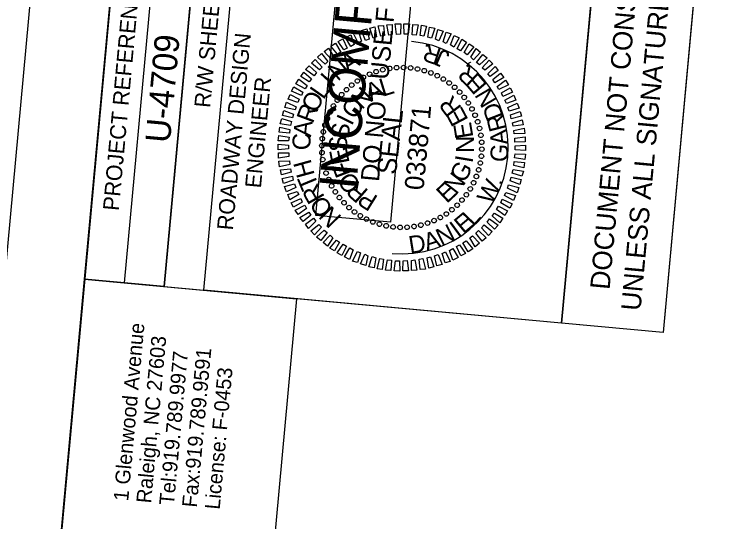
# Model space of a CAD drawing. Extents: x 2012234 to 2013485, y 445892 to 447846.
# Drawn here: x 2012372.3 to 2012600.1, y 447543.6 to 447702.6 of the extents above; entities that cross this region are included whole.
import ezdxf

# ---------------------------------------------------------------- set-up
doc = ezdxf.new("R2010")
doc.units = 0
for name, color, linetype in [('Old_Level_2', 7, 'Continuous'), ('Old_Level_58', 7, 'Continuous'), ('Scratch_Level_0', 7, 'Continuous'), ('Sheet Clip Boundary CELL', 7, 'Continuous'), ('Sheet Data Field CELL', 7, 'Continuous'), ('Sheet Plan And Profile CELL', 7, 'Continuous'), ('Sheet Plot Border Outside CELL', 7, 'Continuous'), ('Sheet Professional Seal CELL', 7, 'Continuous'), ('Sheet Profile Grid Minor CELL', 7, 'Continuous'), ('Sheet Sticker Exception Certification CELL', 7, 'Continuous'), ('Sheet Sticker Incomplete CELL', 7, 'Continuous')]:
    doc.layers.add(name, color=color, linetype=linetype)

msp = doc.modelspace()

# ---------------------------------------------------------------- linework, layer by layer
at = {"layer": 'Old_Level_58'}
msp.add_lwpolyline([(2012375.92, 447420.36), (2012394.24, 447619.57), (2012460.65, 447613.46), (2012442.33, 447414.25)], close=True, dxfattribs=at)
at = {"layer": 'Scratch_Level_0'}
msp.add_arc((2012493.64, 447660.9), 33.36, 264.7467, 84.7467, dxfattribs=at)
at = {"layer": 'Sheet Clip Boundary CELL'}
msp.add_lwpolyline([(2012286.31, 446445.78), (2012511.43, 446429.21), (2012750.66, 446410.08), (2013333.05, 446362.08), (2013458.14, 447722.64), (2012593.82, 447802.11), (2012575.5, 447602.9), (2012460.65, 447613.46), (2012442.34, 447414.28), (2012375.93, 447420.39)], close=True, dxfattribs=at)
at = {"layer": 'Sheet Plan And Profile CELL'}
for p, q in [((2012406.74, 447618.42), (2012425.05, 447817.63)), ((2012419.18, 447617.27), (2012437.5, 447816.48)), ((2012419.18, 447617.27), (2012431.63, 447616.13)), ((2012419.18, 447617.27), (2012431.63, 447616.13))]:
    msp.add_line(p, q, dxfattribs=at)
for points in [[(2012412.56, 447818.78), (2012275.22, 446325.08), (2013320.81, 446228.94), (2013458.14, 447722.64)], [(2012394.24, 447619.57), (2012412.56, 447818.78), (2012437.5, 447816.48), (2012419.18, 447617.27)], [(2012431.63, 447616.13), (2012440.79, 447715.76), (2012552.82, 447705.46), (2012543.66, 447605.83)]]:
    msp.add_lwpolyline(points, close=True, dxfattribs=at)
at = {"layer": 'Sheet Plot Border Outside CELL'}
msp.add_lwpolyline([(2013329.68, 446052.39), (2013485.33, 447745.24), (2012389.95, 447845.96), (2012234.3, 446153.1)], close=True, dxfattribs=at)
at = {"layer": 'Sheet Professional Seal CELL'}
for p, q in [((2012487.65, 447685.3), (2012487.65, 447685.3)), ((2012489.79, 447685.7), (2012489.79, 447685.7)), ((2012492.02, 447685.9), (2012492.02, 447685.9)), ((2012494.19, 447686), (2012494.19, 447686)), ((2012496.39, 447685.85), (2012496.39, 447685.85)), ((2012498.56, 447685.5), (2012498.56, 447685.5)), ((2012481.55, 447682.9), (2012481.55, 447682.9)), ((2012483.55, 447683.87), (2012483.55, 447683.87)), ((2012485.58, 447684.68), (2012485.58, 447684.68)), ((2012500.67, 447684.95), (2012500.67, 447684.95)), ((2012502.72, 447684.31), (2012502.72, 447684.31)), ((2012504.75, 447683.42), (2012504.75, 447683.42)), ((2012479.7, 447681.81), (2012479.7, 447681.81)), ((2012506.66, 447682.34), (2012506.66, 447682.34)), ((2012508.51, 447681.17), (2012508.51, 447681.17)), ((2012476.28, 447679.06), (2012476.28, 447679.06)), ((2012477.92, 447680.47), (2012477.92, 447680.47)), ((2012510.19, 447679.76), (2012510.19, 447679.76)), ((2012474.78, 447677.44), (2012474.78, 447677.44)), ((2012511.81, 447678.26), (2012511.81, 447678.26)), ((2012513.21, 447676.62), (2012513.21, 447676.62)), ((2012472.19, 447673.91), (2012472.19, 447673.91)), ((2012473.37, 447675.76), (2012473.37, 447675.76)), ((2012514.55, 447674.84), (2012514.55, 447674.84)), ((2012471.11, 447672.01), (2012471.11, 447672.01)), ((2012515.64, 447672.98), (2012515.64, 447672.98)), ((2012470.22, 447669.98), (2012470.22, 447669.98)), ((2012516.61, 447670.99), (2012516.61, 447670.99)), ((2012469.58, 447667.93), (2012469.58, 447667.93)), ((2012517.43, 447668.95), (2012517.43, 447668.95)), ((2012518.04, 447666.89), (2012518.04, 447666.89)), ((2012469.04, 447665.82), (2012469.04, 447665.82)), ((2012518.45, 447664.74), (2012518.45, 447664.74)), ((2012468.69, 447663.64), (2012468.69, 447663.64)), ((2012518.64, 447662.51), (2012518.64, 447662.51)), ((2012468.53, 447661.45), (2012468.53, 447661.45)), ((2012493.64, 447660.9), (2012493.64, 447660.9)), ((2012518.74, 447660.35), (2012518.74, 447660.35)), ((2012468.64, 447659.28), (2012468.64, 447659.28)), ((2012518.59, 447658.15), (2012518.59, 447658.15)), ((2012468.83, 447657.05), (2012468.83, 447657.05)), ((2012518.24, 447655.97), (2012518.24, 447655.97)), ((2012469.24, 447654.91), (2012469.24, 447654.91)), ((2012517.7, 447653.86), (2012517.7, 447653.86)), ((2012469.85, 447652.84), (2012469.85, 447652.84)), ((2012517.06, 447651.81), (2012517.06, 447651.81)), ((2012470.67, 447650.81), (2012470.67, 447650.81)), ((2012471.64, 447648.81), (2012471.64, 447648.81)), ((2012516.17, 447649.79), (2012516.17, 447649.79)), ((2012472.72, 447646.95), (2012472.72, 447646.95)), ((2012515.09, 447647.88), (2012515.09, 447647.88)), ((2012474.07, 447645.17), (2012474.07, 447645.17)), ((2012512.5, 447644.35), (2012512.5, 447644.35)), ((2012513.91, 447646.03), (2012513.91, 447646.03)), ((2012475.47, 447643.54), (2012475.47, 447643.54)), ((2012477.09, 447642.03), (2012477.09, 447642.03)), ((2012511, 447642.73), (2012511, 447642.73)), ((2012478.77, 447640.62), (2012478.77, 447640.62)), ((2012507.58, 447639.98), (2012507.58, 447639.98)), ((2012509.36, 447641.32), (2012509.36, 447641.32)), ((2012480.62, 447639.45), (2012480.62, 447639.45)), ((2012482.53, 447638.37), (2012482.53, 447638.37)), ((2012484.56, 447637.48), (2012484.56, 447637.48)), ((2012503.73, 447637.93), (2012503.73, 447637.93)), ((2012505.73, 447638.9), (2012505.73, 447638.9)), ((2012486.61, 447636.84), (2012486.61, 447636.84)), ((2012488.72, 447636.29), (2012488.72, 447636.29)), ((2012490.89, 447635.94), (2012490.89, 447635.94)), ((2012493.09, 447635.79), (2012493.09, 447635.79)), ((2012495.26, 447635.89), (2012495.26, 447635.89)), ((2012497.48, 447636.09), (2012497.48, 447636.09)), ((2012499.63, 447636.5), (2012499.63, 447636.5)), ((2012501.7, 447637.11), (2012501.7, 447637.11))]:
    msp.add_line(p, q, dxfattribs=at)
for points in [[(2012487.1, 447695.74), (2012486.25, 447699.03), (2012487.92, 447699.18), (2012488.18, 447695.99)], [(2012489.55, 447696.12), (2012488.89, 447699.34), (2012490.61, 447699.49), (2012490.62, 447696.32)], [(2012491.98, 447696.35), (2012491.58, 447699.65), (2012493.29, 447699.64), (2012493.19, 447696.44)], [(2012494.4, 447696.43), (2012494.29, 447699.7), (2012496, 447699.64), (2012495.6, 447696.42)], [(2012496.89, 447696.25), (2012497.04, 447699.5), (2012498.73, 447699.34), (2012498.08, 447696.14)], [(2012499.37, 447695.97), (2012499.77, 447699.2), (2012501.41, 447698.94), (2012500.56, 447695.76)], [(2012479.98, 447693.68), (2012478.5, 447696.63), (2012480.1, 447697.14), (2012480.99, 447694.19)], [(2012482.22, 447694.48), (2012480.99, 447697.56), (2012482.65, 447698.06), (2012483.36, 447694.88)], [(2012484.64, 447695.16), (2012483.62, 447698.32), (2012485.22, 447698.73), (2012485.73, 447695.57)], [(2012501.74, 447695.5), (2012502.33, 447698.66), (2012504.01, 447698.3), (2012502.91, 447695.14)], [(2012504.24, 447694.87), (2012504.93, 447697.92), (2012506.59, 447697.41), (2012505.25, 447694.37)], [(2012506.57, 447694), (2012507.51, 447697.03), (2012509.12, 447696.53), (2012507.58, 447693.51)], [(2012475.51, 447691.48), (2012473.65, 447694.12), (2012475.18, 447694.93), (2012476.51, 447691.99)], [(2012477.67, 447692.59), (2012476.02, 447695.4), (2012477.61, 447696.21), (2012478.73, 447693.2)], [(2012508.9, 447693.03), (2012510.08, 447696.04), (2012511.56, 447695.25), (2012509.89, 447692.39)], [(2012511, 447691.84), (2012512.42, 447694.82), (2012513.9, 447693.93), (2012512.04, 447691.24)], [(2012471.48, 447688.59), (2012469.34, 447690.95), (2012470.64, 447692.03), (2012472.35, 447689.26)], [(2012473.43, 447690.17), (2012471.4, 447692.67), (2012472.85, 447693.59), (2012474.49, 447690.77)], [(2012513.19, 447690.63), (2012514.7, 447693.35), (2012516.17, 447692.47), (2012514.09, 447689.95)], [(2012469.57, 447686.96), (2012467.17, 447689.24), (2012468.48, 447690.32), (2012470.41, 447687.84)], [(2012515.23, 447689.24), (2012516.98, 447691.89), (2012518.28, 447690.77), (2012516.05, 447688.36)], [(2012517.08, 447687.56), (2012519.02, 447690.09), (2012520.38, 447689.02), (2012517.97, 447686.83)], [(2012467.86, 447685.21), (2012465.29, 447687.3), (2012466.5, 447688.5), (2012468.64, 447686.09)], [(2012518.83, 447685.89), (2012521.01, 447688.3), (2012522.21, 447687.09), (2012519.67, 447685.11)], [(2012466.18, 447683.3), (2012463.45, 447685.31), (2012464.61, 447686.51), (2012466.87, 447684.35)], [(2012520.57, 447683.98), (2012522.84, 447686.33), (2012523.87, 447684.98), (2012521.29, 447683.11)], [(2012464.65, 447681.49), (2012461.94, 447683.09), (2012462.92, 447684.51), (2012465.34, 447682.38)], [(2012522.16, 447682.17), (2012524.55, 447684.16), (2012525.63, 447682.86), (2012522.77, 447681.16)], [(2012463.3, 447679.3), (2012460.47, 447680.82), (2012461.31, 447682.3), (2012463.95, 447680.35)], [(2012523.52, 447680.04), (2012526.1, 447681.96), (2012527.03, 447680.52), (2012524.08, 447679.04)], [(2012462.15, 447677.15), (2012459.11, 447678.58), (2012459.84, 447679.92), (2012462.6, 447678.26)], [(2012524.84, 447678.01), (2012527.55, 447679.62), (2012528.37, 447678.24), (2012525.33, 447676.86)], [(2012461.04, 447674.99), (2012458.02, 447676.02), (2012458.66, 447677.52), (2012461.49, 447676)], [(2012525.88, 447675.71), (2012528.74, 447677.3), (2012529.39, 447675.68), (2012526.39, 447674.71)], [(2012460.18, 447672.66), (2012456.99, 447673.45), (2012457.54, 447675.11), (2012460.52, 447673.68)], [(2012526.88, 447673.46), (2012529.81, 447674.79), (2012530.37, 447673.18), (2012527.23, 447672.32)], [(2012459.39, 447670.17), (2012456.25, 447670.91), (2012456.65, 447672.53), (2012459.65, 447671.35)], [(2012527.72, 447671.17), (2012530.73, 447672.2), (2012531.19, 447670.65), (2012527.91, 447669.9)], [(2012458.78, 447667.82), (2012455.56, 447668.31), (2012456.01, 447669.93), (2012459.09, 447668.99)], [(2012528.3, 447668.66), (2012531.39, 447669.53), (2012531.69, 447667.94), (2012528.55, 447667.58)], [(2012458.4, 447665.34), (2012455.16, 447665.64), (2012455.36, 447667.28), (2012458.56, 447666.53)], [(2012528.72, 447666.21), (2012531.96, 447666.96), (2012532.15, 447665.24), (2012528.88, 447665.14)], [(2012458.13, 447662.96), (2012454.87, 447663), (2012455.07, 447664.64), (2012458.29, 447664.15)], [(2012529.05, 447663.77), (2012532.31, 447664.27), (2012532.31, 447662.61), (2012529.09, 447662.56)], [(2012458.15, 447660.44), (2012454.91, 447660.19), (2012454.87, 447661.9), (2012458.11, 447661.65)], [(2012529.13, 447661.35), (2012532.37, 447661.6), (2012532.41, 447659.89), (2012529.17, 447660.14)], [(2012458.23, 447658.03), (2012454.97, 447657.52), (2012454.97, 447659.18), (2012458.19, 447659.23)], [(2012529.15, 447658.84), (2012532.41, 447658.79), (2012532.21, 447657.15), (2012528.99, 447657.65)], [(2012458.56, 447655.59), (2012455.32, 447654.83), (2012455.13, 447656.55), (2012458.4, 447656.65)], [(2012528.88, 447656.45), (2012532.12, 447656.15), (2012531.92, 447654.51), (2012528.72, 447655.26)], [(2012458.98, 447653.14), (2012455.89, 447652.27), (2012455.58, 447653.85), (2012458.73, 447654.21)], [(2012528.5, 447653.97), (2012531.72, 447653.48), (2012531.27, 447651.86), (2012528.19, 447652.8)], [(2012459.56, 447650.62), (2012456.55, 447649.59), (2012456.09, 447651.14), (2012459.37, 447651.9)], [(2012527.88, 447651.62), (2012531.03, 447650.88), (2012530.63, 447649.26), (2012527.62, 447650.44)], [(2012460.4, 447648.34), (2012457.47, 447647), (2012456.91, 447648.61), (2012460.05, 447649.47)], [(2012527.1, 447649.13), (2012530.29, 447648.34), (2012529.74, 447646.68), (2012526.76, 447648.11)], [(2012461.4, 447646.09), (2012458.54, 447644.49), (2012457.89, 447646.11), (2012460.89, 447647.09)], [(2012526.24, 447646.8), (2012529.25, 447645.77), (2012528.61, 447644.27), (2012525.79, 447645.79)], [(2012462.44, 447643.78), (2012459.73, 447642.17), (2012458.91, 447643.55), (2012461.94, 447644.93)], [(2012525.13, 447644.64), (2012528.17, 447643.21), (2012527.44, 447641.87), (2012524.68, 447643.53)], [(2012463.76, 447641.75), (2012461.17, 447639.83), (2012460.25, 447641.27), (2012463.2, 447642.76)], [(2012523.98, 447642.49), (2012526.8, 447640.98), (2012525.97, 447639.5), (2012523.33, 447641.45)], [(2012465.12, 447639.62), (2012462.73, 447637.63), (2012461.64, 447638.93), (2012464.51, 447640.63)], [(2012522.63, 447640.31), (2012525.34, 447638.7), (2012524.36, 447637.28), (2012521.94, 447639.41)], [(2012466.71, 447637.81), (2012464.44, 447635.46), (2012463.41, 447636.81), (2012465.99, 447638.68)], [(2012521.1, 447638.49), (2012523.83, 447636.48), (2012522.67, 447635.28), (2012520.4, 447637.45)], [(2012468.44, 447635.9), (2012466.26, 447633.49), (2012465.07, 447634.7), (2012467.61, 447636.68)], [(2012519.42, 447636.58), (2012521.99, 447634.49), (2012520.78, 447633.3), (2012518.64, 447635.7)], [(2012470.2, 447634.23), (2012468.26, 447631.7), (2012466.9, 447632.78), (2012469.31, 447634.96)], [(2012472.05, 447632.55), (2012470.3, 447629.9), (2012469, 447631.03), (2012471.23, 447633.43)], [(2012515.8, 447633.2), (2012517.94, 447630.84), (2012516.64, 447629.76), (2012514.93, 447632.53)], [(2012517.7, 447634.83), (2012520.11, 447632.55), (2012518.8, 447631.47), (2012516.87, 447633.96)], [(2012474.08, 447631.16), (2012472.58, 447628.44), (2012471.1, 447629.33), (2012473.19, 447631.85)], [(2012476.28, 447629.96), (2012474.85, 447626.97), (2012473.38, 447627.86), (2012475.23, 447630.55)], [(2012513.84, 447631.62), (2012515.87, 447629.13), (2012514.43, 447628.2), (2012512.78, 447631.02)], [(2012478.38, 447628.76), (2012477.2, 447625.75), (2012475.72, 447626.54), (2012477.39, 447629.4)], [(2012480.7, 447627.79), (2012479.77, 447624.76), (2012478.16, 447625.26), (2012479.7, 447628.29)], [(2012509.6, 447629.2), (2012511.25, 447626.39), (2012509.67, 447625.58), (2012508.54, 447628.6)], [(2012511.76, 447630.31), (2012513.63, 447627.68), (2012512.1, 447626.86), (2012510.76, 447629.8)], [(2012483.03, 447626.92), (2012482.35, 447623.87), (2012480.69, 447624.38), (2012482.03, 447627.42)], [(2012485.54, 447626.29), (2012484.95, 447623.13), (2012483.27, 447623.49), (2012484.36, 447626.65)], [(2012487.9, 447625.82), (2012487.51, 447622.6), (2012485.87, 447622.85), (2012486.72, 447626.03)], [(2012500.18, 447626.05), (2012501.03, 447622.76), (2012499.36, 447622.61), (2012499.1, 447625.8)], [(2012502.64, 447626.63), (2012503.65, 447623.47), (2012502.06, 447623.07), (2012501.55, 447626.23)], [(2012505.06, 447627.31), (2012506.29, 447624.23), (2012504.63, 447623.73), (2012503.92, 447626.91)], [(2012507.29, 447628.11), (2012508.78, 447625.16), (2012507.18, 447624.65), (2012506.29, 447627.6)], [(2012490.39, 447625.55), (2012490.24, 447622.3), (2012488.55, 447622.45), (2012489.19, 447625.66)], [(2012492.88, 447625.37), (2012492.98, 447622.09), (2012491.28, 447622.15), (2012491.68, 447625.38)], [(2012495.3, 447625.45), (2012495.7, 447622.14), (2012493.99, 447622.15), (2012494.09, 447625.36)], [(2012497.73, 447625.67), (2012498.39, 447622.45), (2012496.67, 447622.31), (2012496.66, 447625.47)]]:
    msp.add_lwpolyline(points, close=True, dxfattribs=at)
for centre, major_axis in [((2012485.58, 447684.65), (-0.231, 0.682)), ((2012487.68, 447685.26), (-0.171, 0.699)), ((2012489.83, 447685.68), (-0.109, 0.712)), ((2012492, 447685.92), (-0.047, 0.718)), ((2012494.19, 447685.97), (0.016, 0.72)), ((2012496.37, 447685.83), (0.078, 0.716)), ((2012498.53, 447685.49), (0.141, 0.706)), ((2012500.66, 447684.97), (0.202, 0.691)), ((2012481.58, 447682.89), (-0.346, 0.631)), ((2012483.54, 447683.85), (-0.29, 0.659)), ((2012502.73, 447684.27), (0.261, 0.671)), ((2012504.73, 447683.39), (0.318, 0.646)), ((2012506.65, 447682.34), (0.374, 0.616)), ((2012477.94, 447680.46), (-0.451, 0.562)), ((2012479.71, 447681.75), (-0.4, 0.599)), ((2012508.47, 447681.12), (0.426, 0.581)), ((2012510.18, 447679.75), (0.475, 0.541)), ((2012476.3, 447679.01), (-0.498, 0.52)), ((2012511.76, 447678.24), (0.52, 0.498)), ((2012473.41, 447675.73), (-0.581, 0.426)), ((2012474.78, 447677.43), (-0.541, 0.475)), ((2012513.2, 447676.59), (0.562, 0.451)), ((2012472.2, 447673.91), (-0.616, 0.374)), ((2012514.49, 447674.83), (0.599, 0.4)), ((2012515.63, 447672.96), (0.631, 0.346)), ((2012471.15, 447671.99), (-0.646, 0.318)), ((2012516.6, 447671), (0.659, 0.29)), ((2012470.27, 447669.99), (-0.671, 0.261)), ((2012517.39, 447668.96), (0.682, 0.231)), ((2012469.56, 447667.92), (-0.691, 0.202)), ((2012518, 447666.86), (0.699, 0.171)), ((2012469.04, 447665.79), (-0.706, 0.141)), ((2012518.43, 447664.71), (0.712, 0.109)), ((2012468.71, 447663.63), (-0.716, 0.078)), ((2012518.67, 447662.53), (0.718, 0.047)), ((2012468.57, 447661.44), (-0.72, 0.016)), ((2012518.71, 447660.35), (0.72, -0.016)), ((2012468.61, 447659.26), (-0.718, -0.047)), ((2012468.85, 447657.08), (-0.712, -0.109)), ((2012518.57, 447658.16), (0.716, -0.078)), ((2012469.28, 447654.94), (-0.699, -0.171)), ((2012518.24, 447656), (0.706, -0.141)), ((2012469.89, 447652.84), (-0.682, -0.231)), ((2012517.72, 447653.88), (0.691, -0.202)), ((2012470.68, 447650.8), (-0.659, -0.29)), ((2012517.01, 447651.8), (0.671, -0.261)), ((2012471.65, 447648.83), (-0.631, -0.346)), ((2012515.08, 447647.88), (0.616, -0.374)), ((2012516.13, 447649.8), (0.646, -0.318)), ((2012472.79, 447646.96), (-0.599, -0.4)), ((2012513.86, 447646.06), (0.581, -0.426)), ((2012474.08, 447645.2), (-0.562, -0.451)), ((2012475.52, 447643.55), (-0.52, -0.498)), ((2012512.49, 447644.36), (0.541, -0.475)), ((2012477.1, 447642.04), (-0.475, -0.541)), ((2012509.34, 447641.34), (0.451, -0.562)), ((2012510.98, 447642.78), (0.498, -0.52)), ((2012478.81, 447640.67), (-0.426, -0.581)), ((2012480.63, 447639.46), (-0.374, -0.616)), ((2012505.7, 447638.91), (0.346, -0.631)), ((2012507.57, 447640.04), (0.4, -0.599)), ((2012482.55, 447638.4), (-0.318, -0.646)), ((2012484.55, 447637.52), (-0.261, -0.671)), ((2012486.62, 447636.82), (-0.202, -0.691)), ((2012499.6, 447636.53), (0.171, -0.699)), ((2012501.7, 447637.15), (0.231, -0.682)), ((2012503.74, 447637.94), (0.29, -0.659)), ((2012488.75, 447636.3), (-0.141, -0.706)), ((2012490.91, 447635.97), (-0.078, -0.716)), ((2012493.09, 447635.82), (-0.016, -0.72)), ((2012495.28, 447635.87), (0.047, -0.718)), ((2012497.45, 447636.11), (0.109, -0.712))]:
    msp.add_ellipse(centre, major_axis=major_axis, ratio=0.999708, dxfattribs=at)
at = {"layer": 'Sheet Sticker Exception Certification CELL'}
for p, q in [((2012543.64, 447605.83), (2012561.96, 447805.04)), ((2012593.8, 447802.11), (2012575.49, 447602.9)), ((2012575.49, 447602.9), (2012543.64, 447605.83))]:
    msp.add_line(p, q, dxfattribs=at)
at = {"layer": 'Sheet Sticker Incomplete CELL'}
msp.add_lwpolyline([(2012490.08, 447637.42), (2012466.67, 447639.57), (2012480.13, 447785.95), (2012503.53, 447783.8)], close=True, dxfattribs=at)

# ---------------------------------------------------------------- texts
at = {"layer": 'Old_Level_2'}
for s, p in [('1 Glenwood Avenue', (2012407.88, 447549.82)), ('Raleigh, NC 27603', (2012415.04, 447549.16)), ('Tel:919.789.9977 ', (2012422.21, 447548.51)), ('Fax:919.789.9591', (2012429.37, 447547.85)), ('License: F-0453', (2012436.54, 447547.19))]:
    msp.add_text(s, height=4.6576, rotation=84.7467, dxfattribs=at).set_placement(p)
at = {"layer": 'Sheet Data Field CELL'}
msp.add_text('U-4709', height=7.75, rotation=84.7467, dxfattribs=at).set_placement((2012420.95, 447662.1))
at = {"layer": 'Sheet Plan And Profile CELL'}
for s, height, p in [('PROJECT REFERENCE NO.', 5.0001, (2012404.93, 447640.88)), ('R/W SHEET NO.', 5.0001, (2012433.56, 447673.19)), ('ROADWAY DESIGN', 5.0001, (2012440.68, 447634.78)), ('ENGINEER', 5, (2012449.47, 447647.98))]:
    msp.add_text(s, height=height, rotation=84.7467, dxfattribs=at).set_placement(p)
at = {"layer": 'Sheet Professional Seal CELL'}
for s, height, rotation, p in [('A', 5.64, 33.3638, (2012476.75, 447684.14)), ('N', 5.64, 40.5656, (2012473.54, 447681.47)), ('I', 5.64, 47.7668, (2012471.8, 447679.47)), ('A', 5.64, 26.5069, (2012484, 447675.14)), ('L', 5.64, 17.1475, (2012487.62, 447676.76)), ('L', 5.64, 54.9675, (2012469.04, 447675.66)), ('N', 5.64, 45.2233, (2012481.15, 447672.54)), ('O', 5.64, 62.1678, (2012466.79, 447671.45)), ('O', 5.64, 54.5801, (2012478.85, 447669.39)), ('R', 5.64, 127.2281, (2012512.61, 447673.31)), ('R', 5.64, 69.3678, (2012465.74, 447668.18)), ('E', 5.64, 117.8707, (2012514.62, 447669.56)), ('SEAL', 5.998, 83.7467, (2012491.83, 447652.17)), ('I', 5.64, 63.9363, (2012477.97, 447667.46)), ('A', 5.64, 83.767, (2012465.16, 447664.02)), ('S', 5.64, 82.6471, (2012476.88, 447663.24)), ('E', 5.64, 99.1584, (2012516.08, 447664.11)), ('C', 5.64, 90.9665, (2012465.09, 447660.06)), ('S', 5.64, 92.0023, (2012476.6, 447659.65)), ('N', 5.64, 89.803, (2012516.22, 447659.12)), ('E', 5.64, 101.3577, (2012477.33, 447656.12)), ('I', 5.64, 80.4479, (2012515.77, 447655.8)), ('H', 5.64, 105.3661, (2012466.39, 447652.31)), ('F', 5.64, 110.7137, (2012478.53, 447652.8)), ('G', 5.64, 61.7369, (2012513.27, 447649.45)), ('T', 5.64, 112.5664, (2012467.73, 447648.92)), ('O', 5.64, 129.4279, (2012481.17, 447649.24)), ('N', 5.64, 52.3806, (2012510.69, 447645.87)), ('R', 5.64, 119.7672, (2012469.61, 447645.33)), ('R', 5.64, 138.7863, (2012483.45, 447647.27)), ('E', 5.64, 43.0235, (2012507.72, 447643.13)), ('O', 5.64, 126.9684, (2012472.38, 447641.61)), ('P', 5.64, 148.1455, (2012486.49, 447645.39)), ('N', 5.64, 134.1702, (2012475.06, 447639.06))]:
    msp.add_text(s, height=height, rotation=rotation, dxfattribs=at).set_placement(p)
at = {"layer": 'Sheet Profile Grid Minor CELL'}
for s, height, rotation, p in [('R', 5.5, 162.1007, (2012506.43, 447691.83)), ('.', 5.5, 169.0272, (2012502.6, 447693.14)), ('J', 5.5, 157.2322, (2012509.01, 447690.63)), (',', 5.5, 144.0519, (2012515.38, 447686.34)), ('R', 5.5, 137.1254, (2012518.29, 447683.54)), ('E', 5.5, 130.5425, (2012520.72, 447680.56)), ('N', 5.5, 120.6107, (2012523.71, 447675.59)), ('D', 5.5, 111.4661, (2012525.66, 447670.63)), ('033871', 5.998, 84.7467, (2012500.43, 447647.32)), ('R', 5.5, 104.5397, (2012526.6, 447666.69)), ('A', 5.5, 96.3539, (2012527.09, 447661.94)), ('G', 5.5, 86.4222, (2012526.77, 447656.16)), ('W', 5.5, 61.6358, (2012521.73, 447642.7)), ('.', 5.5, 73.2419, (2012524.82, 447648.73)), ('E', 5.5, 39.7975, (2012512.95, 447633.56)), ('L', 5.5, 46.3805, (2012515.96, 447635.95)), ('I', 5.5, 36.277, (2012511.23, 447632.42)), ('N', 5.5, 26.3453, (2012506.06, 447629.82)), ('D', 5.5, 9.0149, (2012496.24, 447627.53)), ('A', 5.5, 18.1595, (2012501.51, 447628.36))]:
    msp.add_text(s, height=height, rotation=rotation, dxfattribs=at).set_placement(p)
at = {"layer": 'Sheet Sticker Exception Certification CELL'}
for s, p in [('UNLESS ALL SIGNATURES COMPLETED', (2012568.42, 447609.47)), ('DOCUMENT NOT CONSIDERED FINAL', (2012558.73, 447616.12))]:
    msp.add_text(s, height=6.124, rotation=84.7467, dxfattribs=at).set_placement(p)
at = {"layer": 'Sheet Sticker Incomplete CELL'}
for s, height, p in [('INCOMPLETE PLANS', 11.52, (2012479.24, 447647.4)), ('DO NOT USE FOR R/W ACQUISITION', 5.76, (2012486.46, 447650))]:
    msp.add_text(s, height=height, rotation=84.7467, dxfattribs=at).set_placement(p)

doc.saveas('drawing.dxf')
